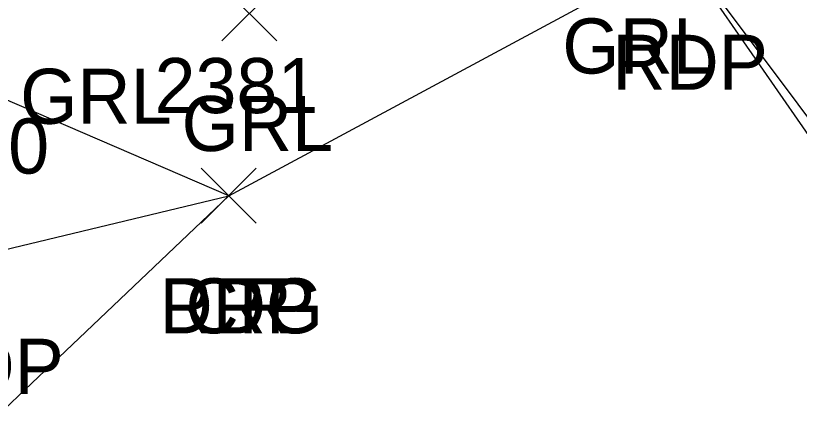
# Model space of a CAD drawing. Extents: x 1653135 to 1655489, y 602711 to 605684.
# Drawn here: x 1653718.91 to 1653747.36, y 605260.26 to 605274.81 of the extents above; entities that cross this region are included whole.
import ezdxf

# ---------------------------------------------------------------- set-up
doc = ezdxf.new("R2010")
doc.units = 0
for name, color, linetype in [('BSE', 7, 'Continuous'), ('P_A', 7, 'Continuous'), ('P_I', 7, 'Continuous'), ('P_TIC', 7, 'Continuous'), ('PET', 7, 'Continuous'), ('PRC', 7, 'Continuous'), ('R_A', 7, 'Continuous'), ('R_I', 7, 'Continuous'), ('R_TIC', 7, 'Continuous'), ('RDG', 7, 'Continuous')]:
    doc.layers.add(name, color=color, linetype=linetype)

msp = doc.modelspace()

# ---------------------------------------------------------------- linework, layer by layer
at = {"layer": 'BSE'}
msp.add_lwpolyline([(1653770.7, 605239.52), (1653755.93, 605260.1), (1653741.57, 605279.28)], dxfattribs=at)
at = {"layer": 'P_TIC'}
for points in [[(1653725.648, 605267.269), (1653727.648, 605269.269)], [(1653727.648, 605267.269), (1653725.648, 605269.269)], [(1653725.648, 605267.269), (1653727.648, 605269.269)], [(1653727.648, 605267.269), (1653725.648, 605269.269)], [(1653725.648, 605267.269), (1653727.648, 605269.269)], [(1653727.648, 605267.269), (1653725.648, 605269.269)], [(1653725.648, 605267.269), (1653727.648, 605269.269)], [(1653727.648, 605267.269), (1653725.648, 605269.269)]]:
    msp.add_lwpolyline(points, dxfattribs=at)
at = {"layer": 'PET'}
msp.add_lwpolyline([(1653654.524, 605279.776), (1653665.481, 605274.477), (1653678.068, 605269.653), (1653696.029, 605266.473), (1653709.03, 605265.366), (1653717.526, 605266.073), (1653726.648, 605268.269), (1653743.088, 605277.115), (1653755.463, 605259.253), (1653765.921, 605244.563), (1653757.558, 605236.881), (1653747.498, 605222.75), (1653729.711, 605207.167), (1653718.29, 605197.382), (1653709.642, 605189.343), (1653699.377, 605174.783), (1653695.369, 605174.396), (1653690.143, 605165.647), (1653683.772, 605149.176), (1653674.351, 605119.826), (1653662.023, 605081.754)], dxfattribs=at)
at = {"layer": 'PRC'}
msp.add_lwpolyline([(1653726.648, 605268.269), (1653711.087, 605253.466), (1653692.662, 605235.598), (1653674.715, 605225.537), (1653647.978, 605202.943)], dxfattribs=at)
at = {"layer": 'R_TIC'}
for points in [[(1653726.394, 605273.891), (1653728.394, 605275.891)], [(1653728.394, 605273.891), (1653726.394, 605275.891)], [(1653726.394, 605273.891), (1653728.394, 605275.891)], [(1653728.394, 605273.891), (1653726.394, 605275.891)], [(1653725.648, 605267.269), (1653727.648, 605269.269)], [(1653727.648, 605267.269), (1653725.648, 605269.269)], [(1653725.648, 605267.269), (1653727.648, 605269.269)], [(1653727.648, 605267.269), (1653725.648, 605269.269)]]:
    msp.add_lwpolyline(points, dxfattribs=at)
at = {"layer": 'RDG'}
msp.add_lwpolyline([(1653726.648, 605268.269), (1653714.889, 605273.34), (1653702.376, 605281.724)], dxfattribs=at)

# ---------------------------------------------------------------- texts
at = {"layer": 'P_A'}
for s, p in [('RDP', (1653740.576, 605272.115)), ('RDP', (1653740.576, 605272.115)), ('RDP', (1653724.136, 605263.269)), ('RDP', (1653724.136, 605263.269)), ('CR', (1653725.081, 605263.269)), ('CR', (1653725.081, 605263.269)), ('RDP', (1653715.014, 605261.073)), ('RDP', (1653715.014, 605261.073))]:
    msp.add_text(s, height=2, dxfattribs=at).set_placement(p)
at = {"layer": 'P_I'}
for s, p in [('2381', (1653723.955, 605271.269)), ('2381', (1653723.955, 605271.269)), ('2381', (1653723.955, 605271.269)), ('2381', (1653723.955, 605271.269)), ('2380', (1653714.18, 605269.073)), ('2380', (1653714.18, 605269.073))]:
    msp.add_text(s, height=2, dxfattribs=at).set_placement(p)
at = {"layer": 'R_A'}
for s, p in [('GRL', (1653738.76, 605272.707)), ('GRL', (1653738.76, 605272.707)), ('GRL', (1653719.077, 605270.88)), ('GRL', (1653719.077, 605270.88)), ('GRL', (1653724.938, 605269.891)), ('GRL', (1653724.938, 605269.891)), ('DRG', (1653724.136, 605263.269)), ('DRG', (1653724.136, 605263.269))]:
    msp.add_text(s, height=2, dxfattribs=at).set_placement(p)
at = {"layer": 'R_I'}
msp.add_text('2381', height=2, dxfattribs=at).set_placement((1653723.955, 605271.269))
msp.add_text('2381', height=2, dxfattribs=at).set_placement((1653723.955, 605271.269))

doc.saveas('drawing.dxf')
